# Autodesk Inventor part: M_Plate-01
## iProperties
Company: Autodes, Inc
Created: 2005-03
Part Number: M_Plate-01
Document SubType Name: Modeling
Stock Number: M_Plate-01
Density: 1 g/cm^3
Author: Admin
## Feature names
1. Extrusion1
2. Extrusion2
3. Extrusion3
4. Hole1
5. Hole2
